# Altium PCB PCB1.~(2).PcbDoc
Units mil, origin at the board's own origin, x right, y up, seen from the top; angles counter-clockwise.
Board outline 1968 x 1968 mil, 4 copper layers (Top Layer, Internal Plane 1, Internal Plane 2, Bottom Layer), stack 18.2 mil thick; 12 components, 11 nets, 37 pads, 0 vias.
Unrouted connection lines stored in the file: 6.
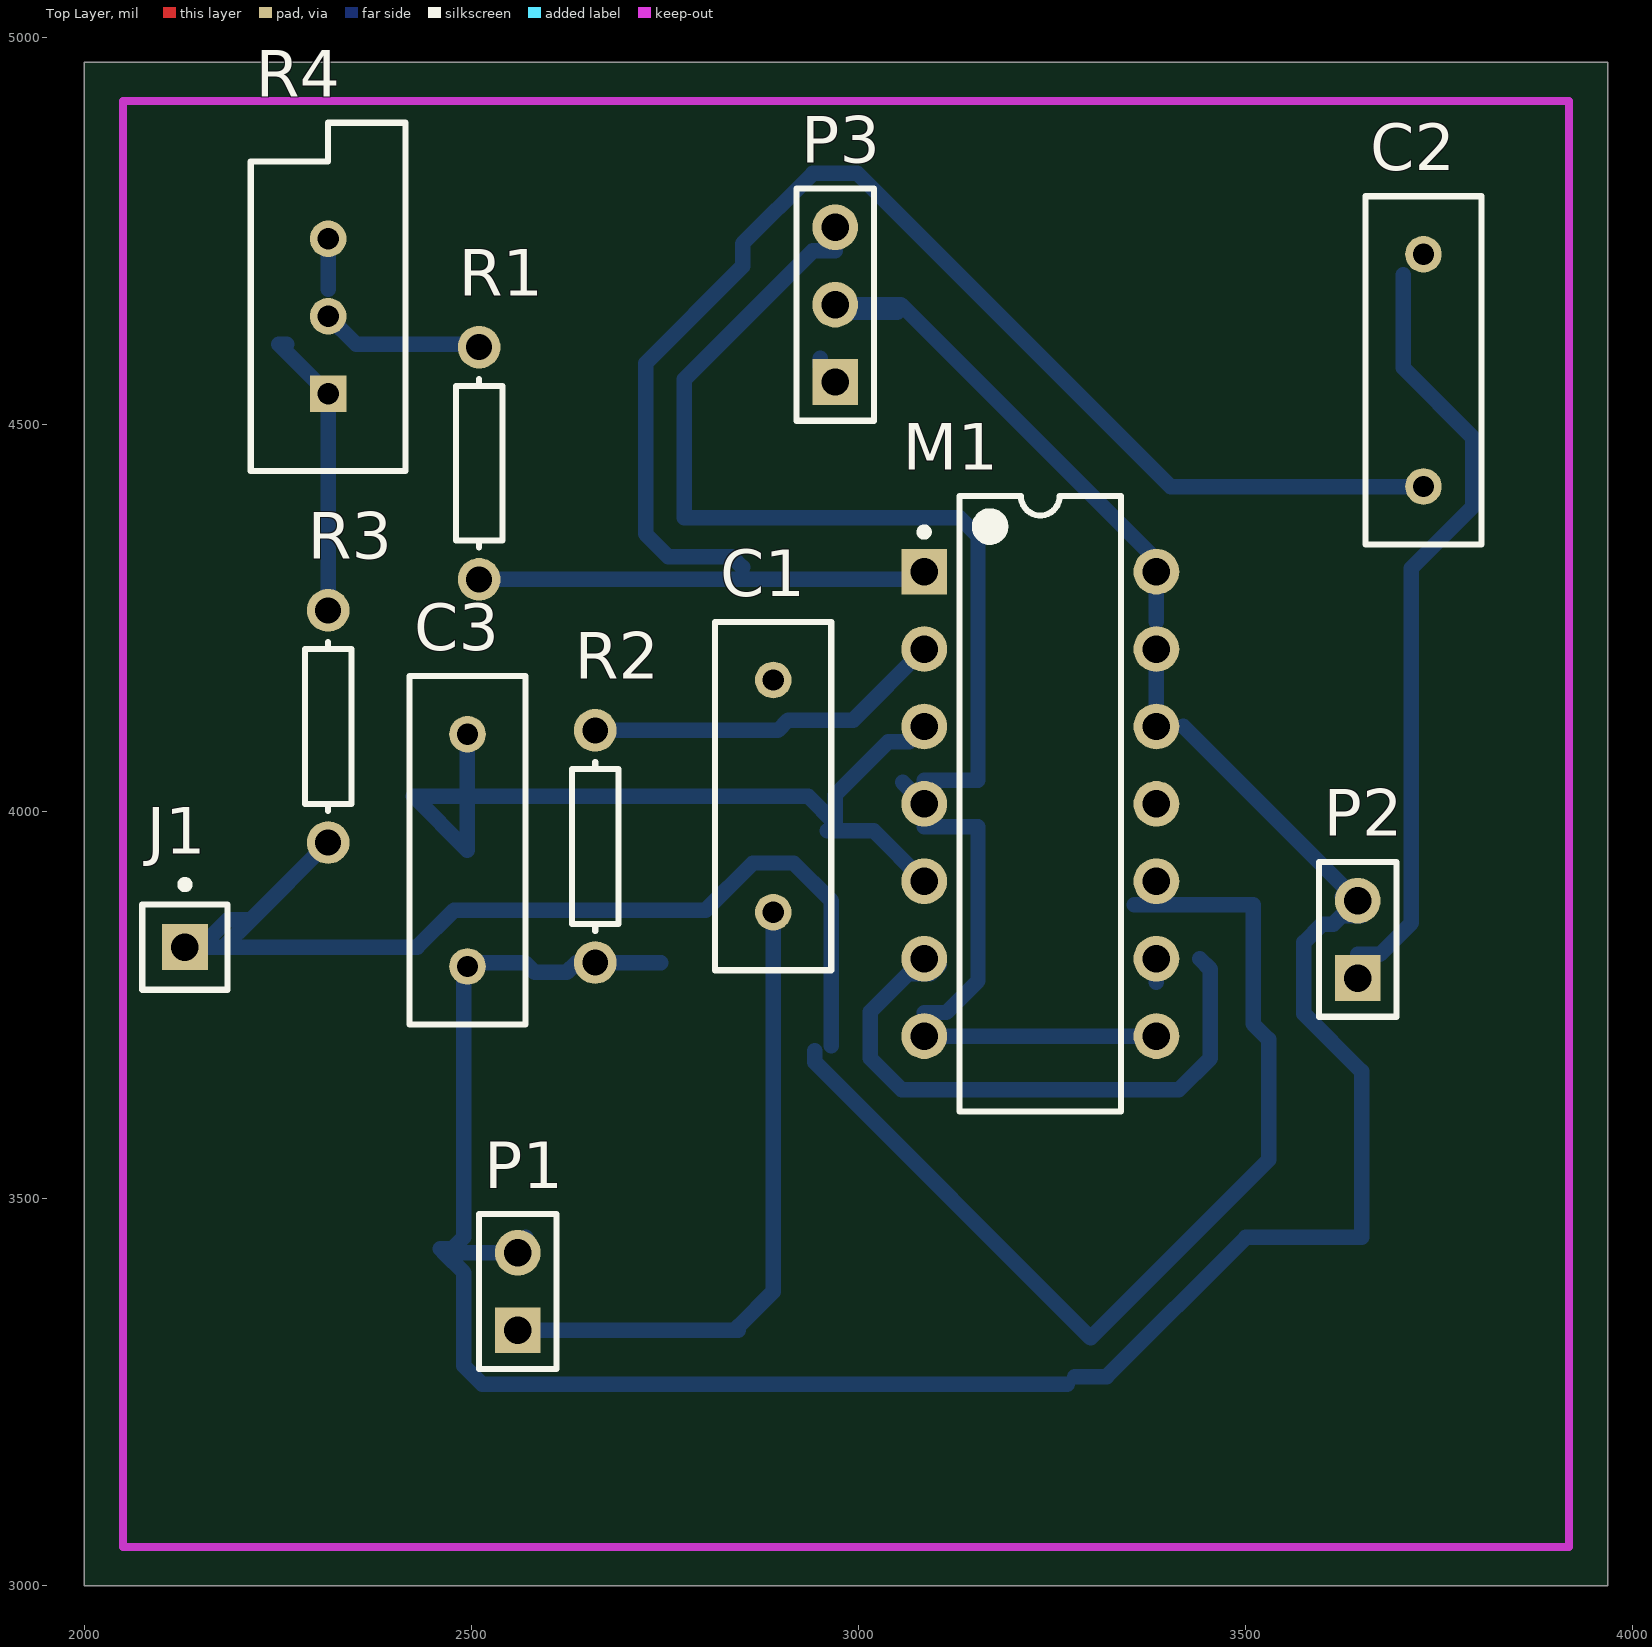
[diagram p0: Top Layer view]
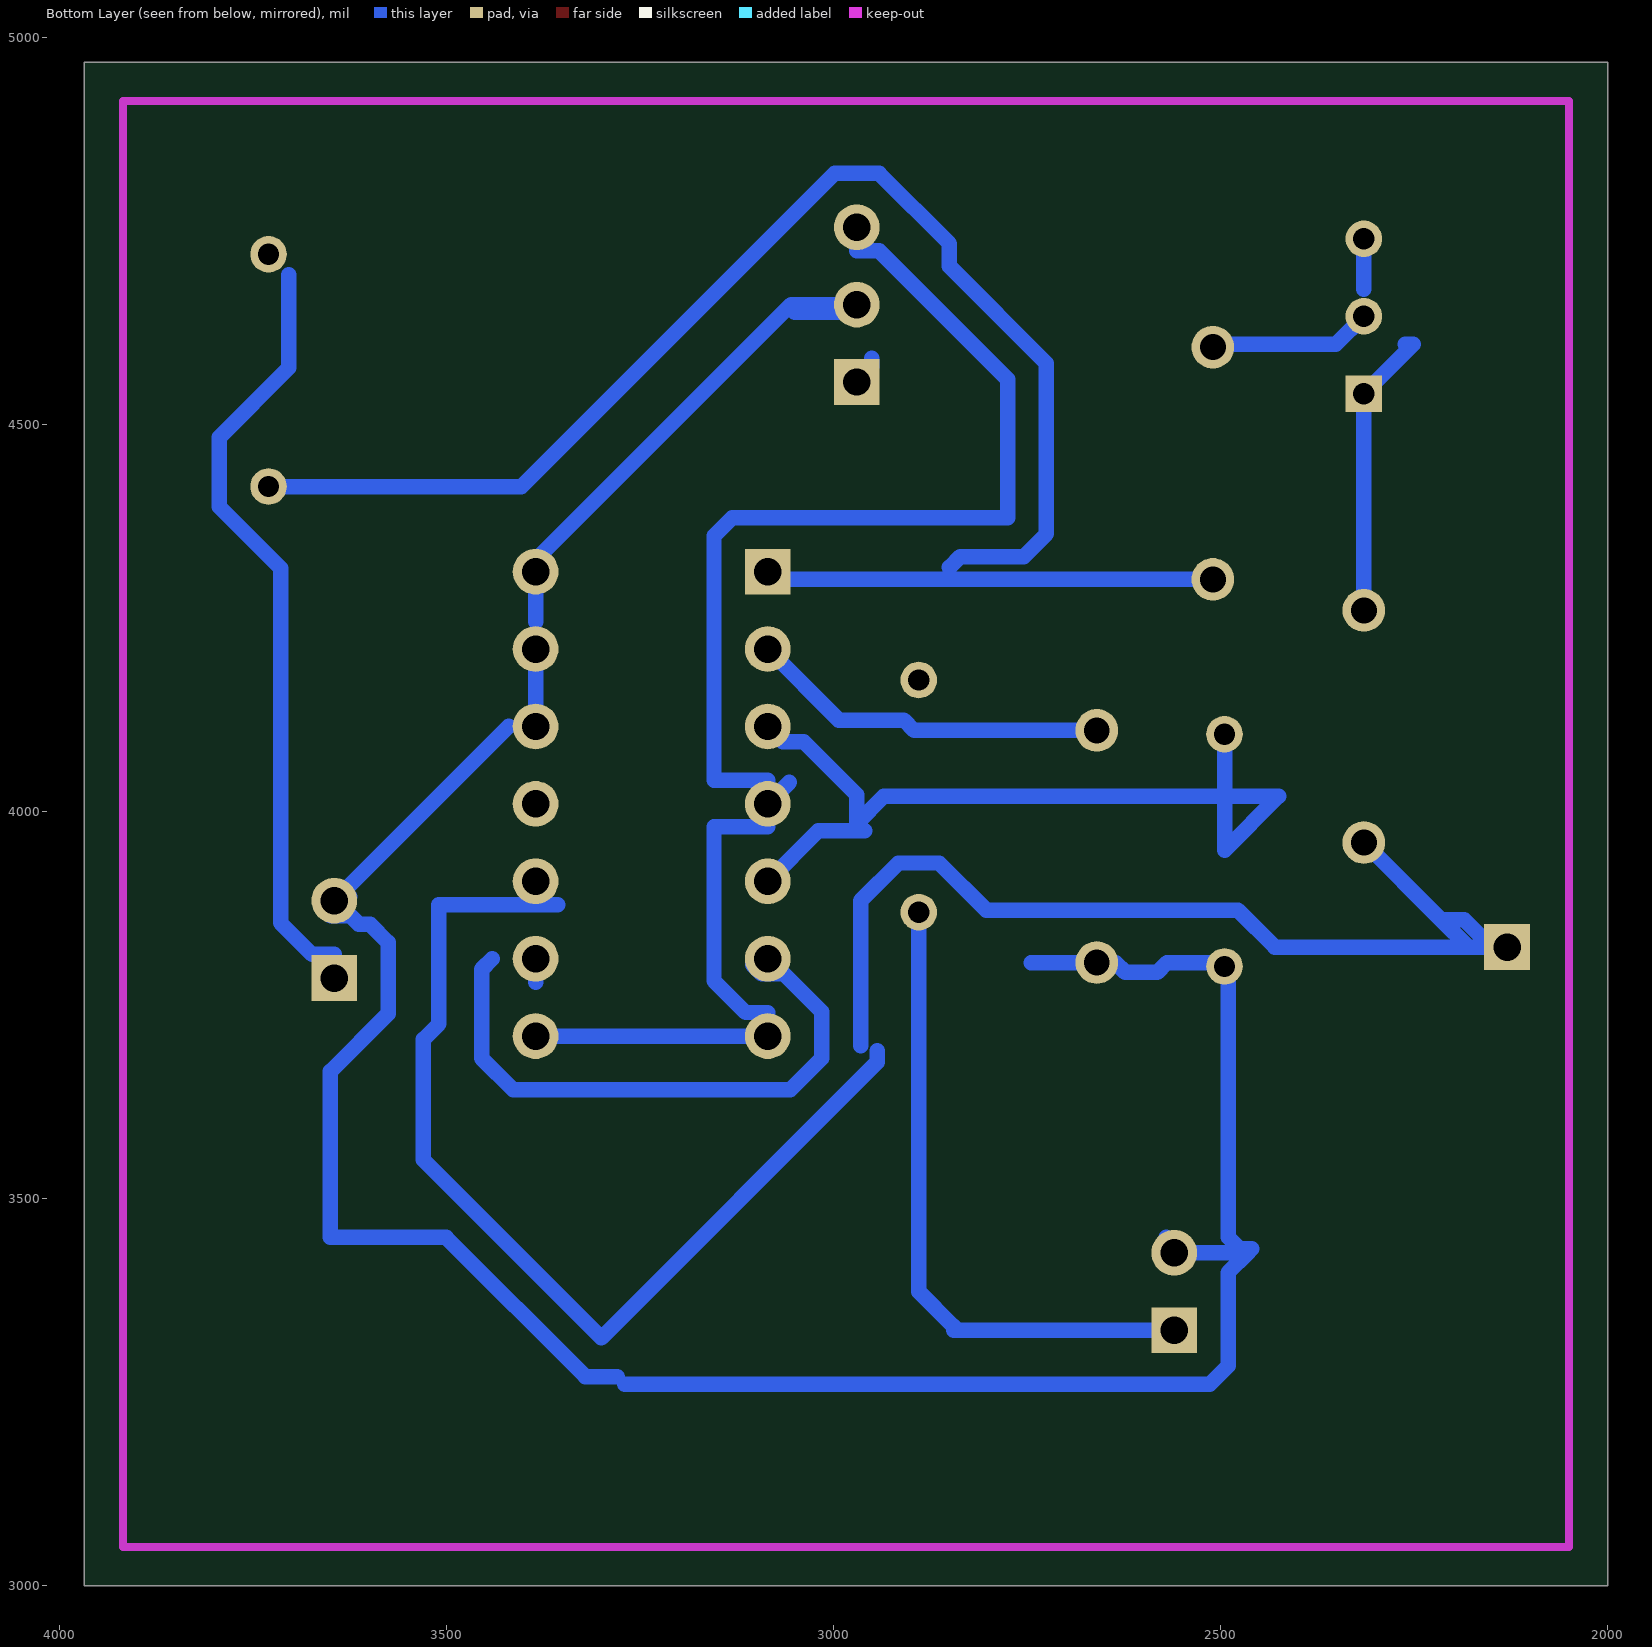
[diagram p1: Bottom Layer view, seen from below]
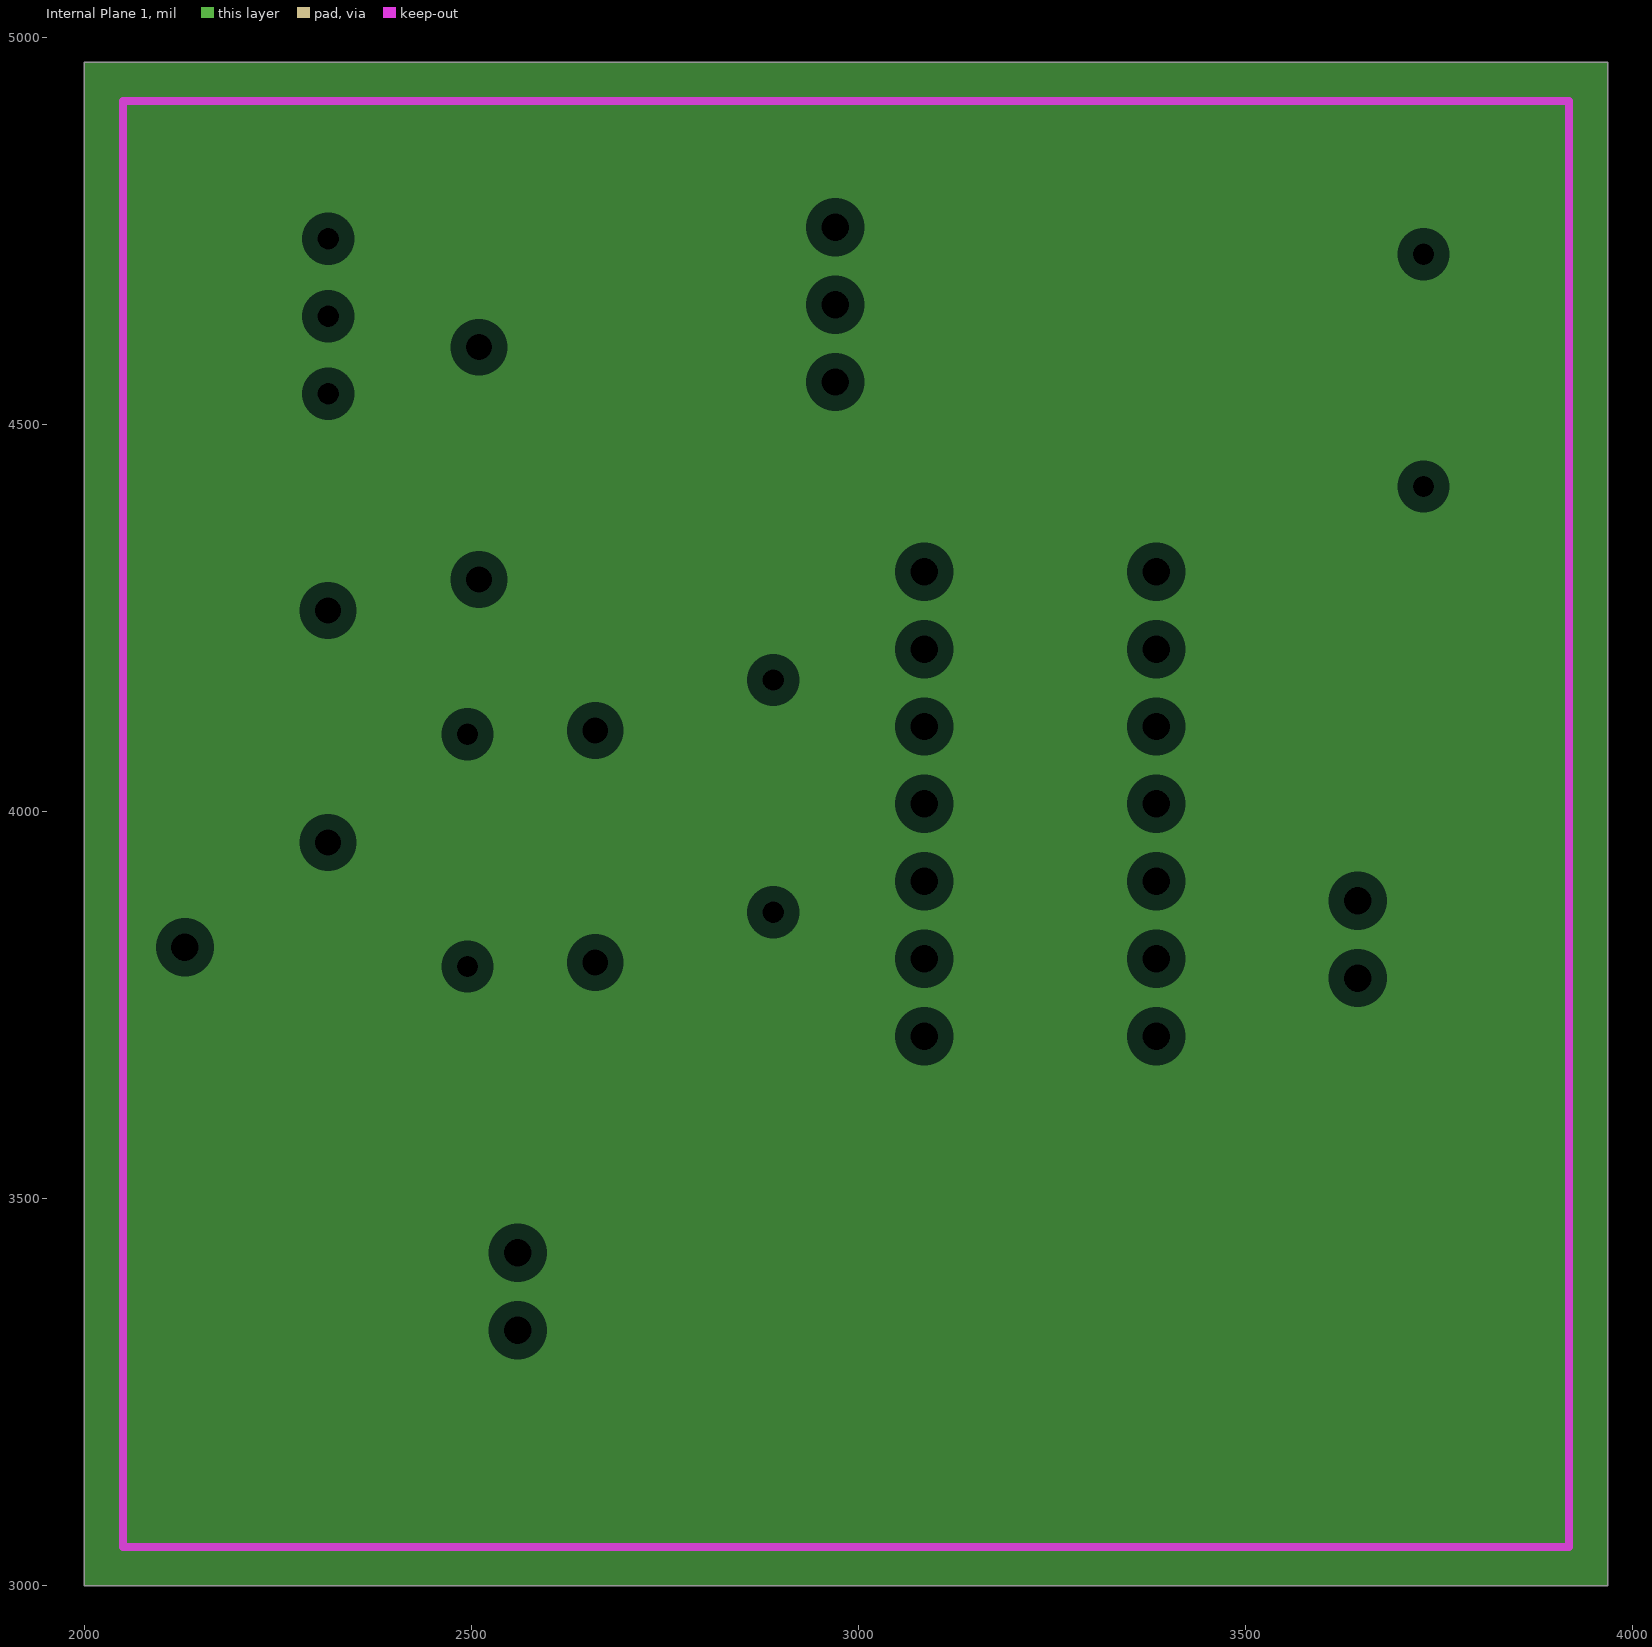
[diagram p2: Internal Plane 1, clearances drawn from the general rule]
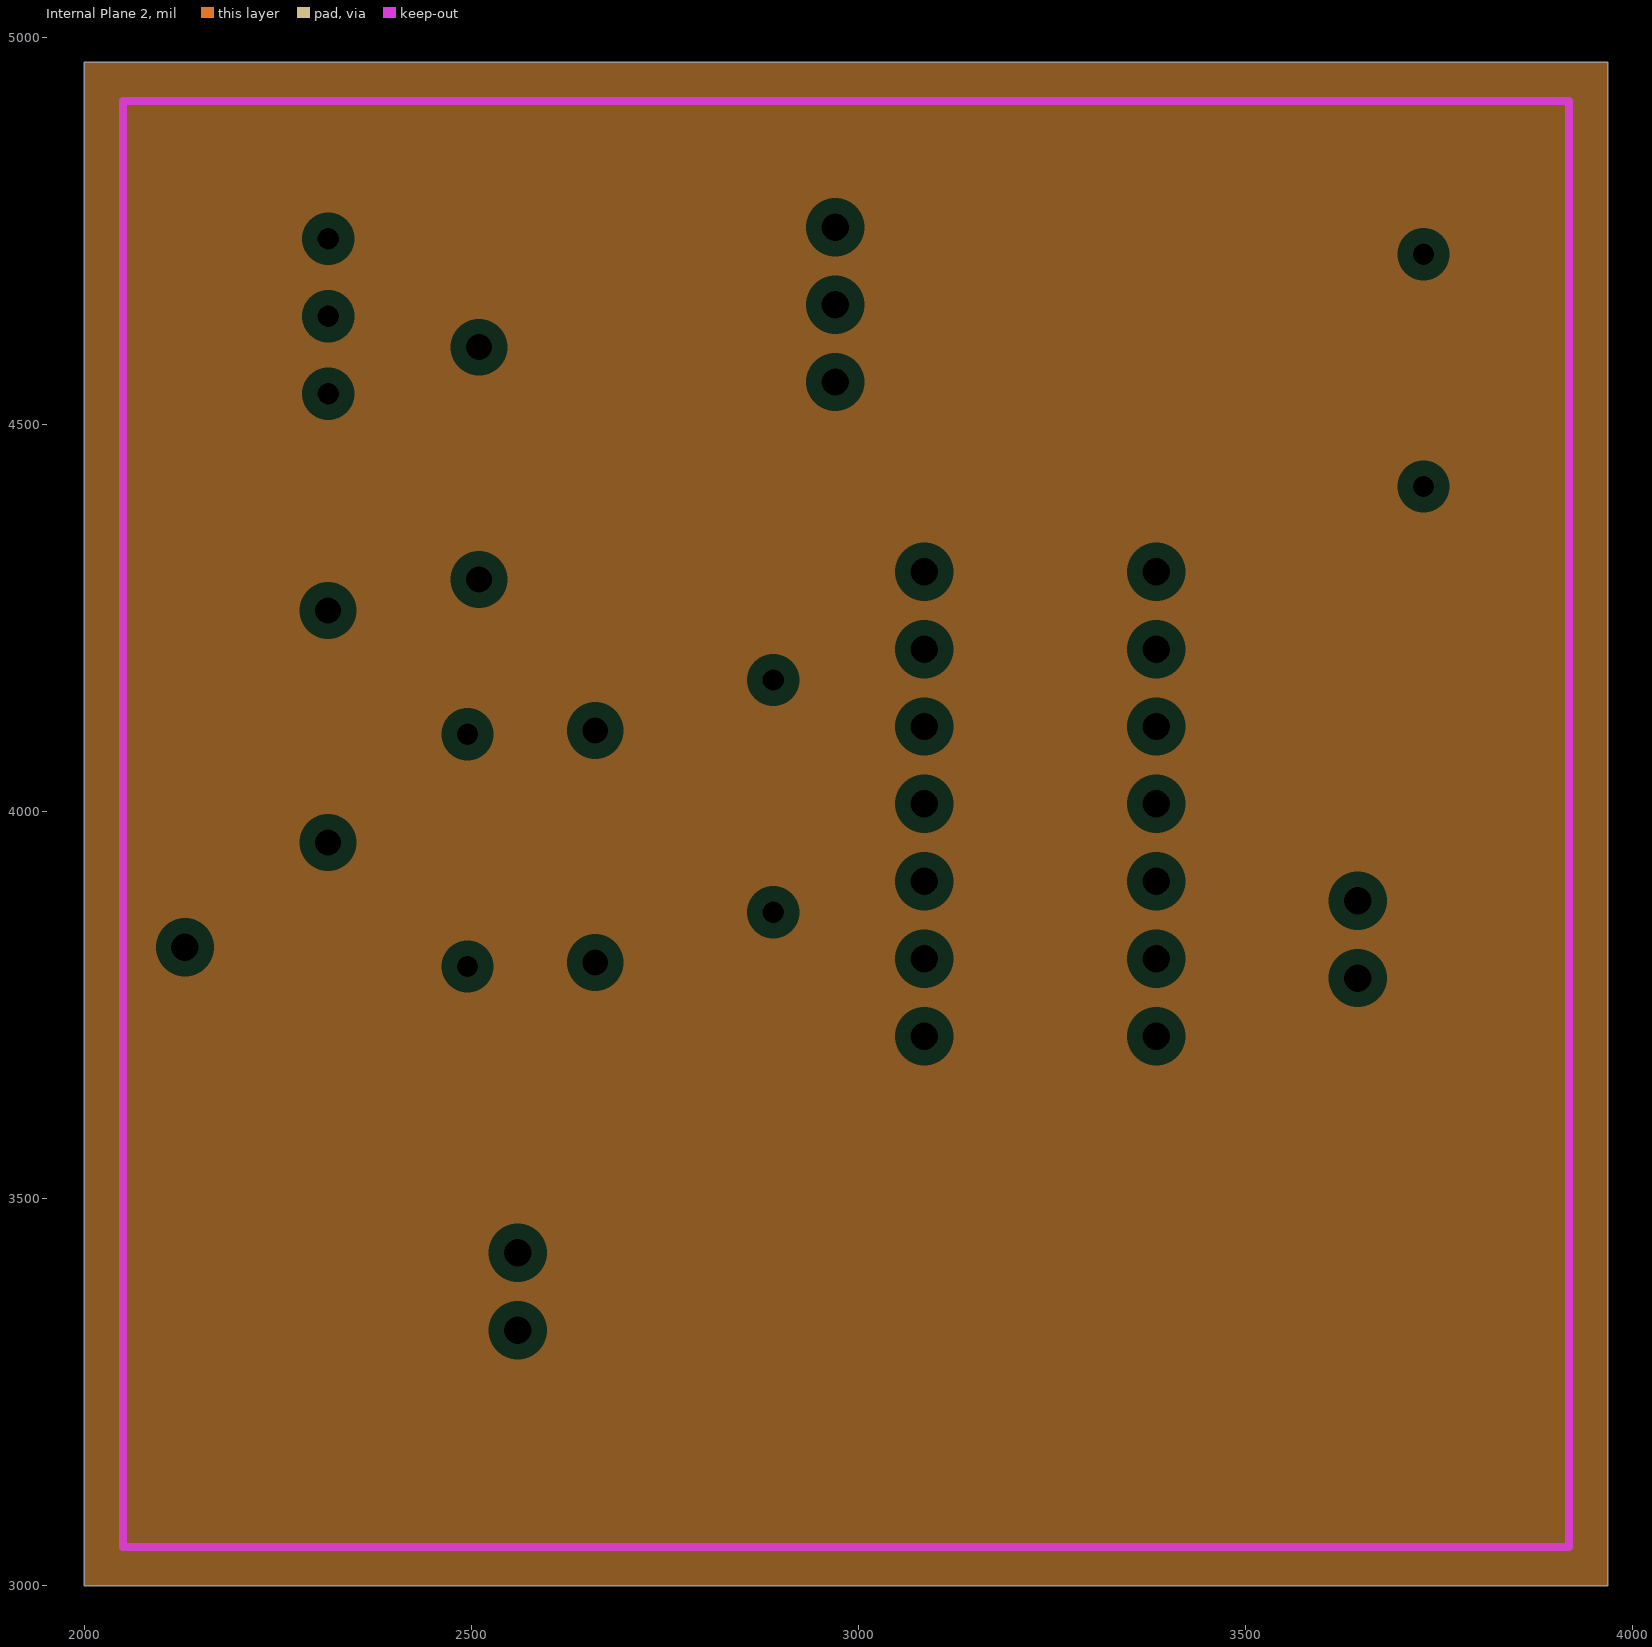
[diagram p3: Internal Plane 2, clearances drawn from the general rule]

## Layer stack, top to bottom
Top Solder: solder mask 0.4, Solder Resist, Dk 3.5
Top Layer: signal copper 1.4
Internal Plane 1: plane copper 1.4
Internal Plane 2: plane copper 1.4
Dielectric 1: dielectric 12.6, FR-4, Dk 4.8
Bottom Layer: signal copper 1.4
Bottom Solder: solder mask 0.4, Solder Resist, Dk 3.5

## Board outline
2000,3000 3968,3000 3968,4968 2000,4968

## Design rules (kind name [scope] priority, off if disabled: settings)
Clearance [All] p1: gap=30
PlaneClearance [All] p1: clearance=20
PlaneConnect [All] p1: planeconnectstyle=Relief reliefexpansion=20 reliefentries=4 reliefconductorwidth=10 reliefairgap=10
PolygonConnect [All] p1: connectstyle=Relief reliefconductorwidth=10 reliefentries=4 polygonreliefangle="90 Angle" airgapwidth=10
RoutingVias [All] p1: holewidth=32 width=62 viastyle="Through Hole" minholewidth=28 minwidth=50 maxholewidth=28 maxwidth=50
SolderMaskExpansion [All] p1: expansion=4
Width [All] p1: maxlimit=20 minlimit=20 preferedwidth=20
28 further rules are at their usual default settings.

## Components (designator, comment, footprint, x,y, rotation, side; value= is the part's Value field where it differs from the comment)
C1 "Cap" RAD-0.3 2890,4020 r90 top
C2 "Cap" RAD-0.3 3730,4570 r90 top
C3 "Cap" RAD-0.3 2495,3950 r90 top
J1 "Socket" PIN1 2130,3825 r0 top
M1 "ALD1106" DIP-14 3235,4010 r0 top
P1 "Header 2" HDR1X2 2560,3330 r90 top
P2 "Header 2" HDR1X2 3645,3785 r90 top
P3 "Header 3" HDR1X3 2970,4555 r90 top
R1 "Res1" AXIAL-0.3 2510,4450 r90 top
R2 "Res1" AXIAL-0.3 2660,3955 r90 top
R3 "Res1" AXIAL-0.3 2315,4110 r90 top
R4 "RPot" VR5 2315,4640 r90 top

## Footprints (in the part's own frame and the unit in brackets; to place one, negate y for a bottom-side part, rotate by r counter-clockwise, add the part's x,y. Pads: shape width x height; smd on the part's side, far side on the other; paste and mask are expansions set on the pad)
AXIAL-0.3 [mm] "Axial Device, Thru-Hole; 2 Leads; 0.3 in Pin Spacing"
  round 1.4 hole 0.85: 1(-3.81,0) 2(3.81,0)
  silkscreen extent -2.77,-0.76 2.77,0.76
DIP-14 [mm] "DIP, 14-Pin, Row Spacing 7.62 mm, Pitch 2.54 mm"
  rect 1.5x1.5 hole 0.9: 1(-3.81,7.62)
  round 1.5 hole 0.9: 2(-3.81,5.08) 3(-3.81,2.54) 4(-3.81,0) 5(-3.81,-2.54) 6(-3.81,-5.08) 7(-3.81,-7.62) 8(3.81,-7.62) 9(3.81,-5.08) 10(3.81,-2.54) 11(3.81,0) 12(3.81,2.54) 13(3.81,5.08) 14(3.81,7.62)
  silkscreen extent -3.93,-10.1 2.65,10.1, body extent -3.6,-10.1 3.6,10.1, height 5.08
HDR1X2 [mm] "Connector; Header; 2 Position"
  rect 1.5x1.5 hole 0.9: 1(0,0)
  round 1.5 hole 0.9: 2(2.54,0)
  silkscreen extent -1.27,-1.27 3.81,1.27
HDR1X3 [mm] "Connector; Header; 3 Position"
  rect 1.5x1.5 hole 0.9: 1(0,0)
  round 1.5 hole 0.9: 2(2.54,0) 3(5.08,0)
  silkscreen extent -1.27,-1.27 6.35,1.27
PIN1 [mm] "Connector; Plug"
  rect 1.5x1.5 hole 0.9: 1(0,0)
  silkscreen extent -1.4,-1.4 1.4,2.17
RAD-0.3 [mm] "Radial Cap, Thru-Hole; 2 Leads; 0.3 in Pin Spacing"
  round 1.2 hole 0.7: 1(-3.81,0) 2(3.81,0)
  silkscreen extent -5.71,-1.91 5.71,1.91
VR5 [mm] "Thru-Hole; 3 Leads"
  rect 1.2x1.2 hole 0.7: 1(-2.54,0)
  round 1.2 hole 0.7: 2(0,0) 3(2.54,0)
  silkscreen extent -5.08,-2.54 6.35,2.54

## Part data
C1 C2 C3: "Capacitor"
M1: "Quad N-channel matched MOSFET array"
P1 P2: "Header, 2-Pin"
P3: "Header, 3-Pin"
R1 R2 R3: "Resistor"
R4: "Potentiometer"

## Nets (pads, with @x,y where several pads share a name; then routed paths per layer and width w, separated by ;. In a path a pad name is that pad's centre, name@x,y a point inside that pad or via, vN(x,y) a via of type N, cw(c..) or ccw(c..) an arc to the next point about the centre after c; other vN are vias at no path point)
GND: C3.1 M1.12 M1.13 M1.14 P1.2 P2.2 P3.2 R2.1 | length 3856.8
  Bottom Layer w20: C3.1 2490,3800 2490,3450 2475,3435 2460,3435 2465,3430 ; C3.1@2500,3805 2569.29,3805 2581.79,3792.5 2623.21,3792.5 2635.71,3805 2745,3805 ; P1.2@2555,3435 P1.2@2570,3450 ; P1.2 2465,3430 ; 3050,4645 2960,4645 P3.2 3055,4655 M1.14@3385,4325 ; 3269.76,3260.47 2513.9,3260.47 2490.47,3283.9 2490.47,3404.53 2465,3430 ; 3279.29,3270 3320.71,3270 3500.71,3450 3650,3450 3650,3664.38 3575.47,3738.9 3575.47,3831.1 3598.9,3854.53 3613.34,3854.53 3624.29,3865.47 3649.53,3865.47 P2.2@3625,3890 ; M1.12 M1.13 ; 3385,4245 3385,4305 3390,4305 M1.14 ; 3420,4110 P2.2 P2.2@3630,3885
NetC1_1: C1.1 P1.1 | length 838.6
  Bottom Layer w20: P1.1 2845,3330 ; 2845,3335 2890,3380 C1.1
NetC1_2: C1.2 M1.2 R2.2 | length 463.5
  Bottom Layer w20: R2.2 2740,4105 ; 2745,4105 2895.96,4105 2909.29,4118.33 2993.33,4118.33 M1.2
NetC2_1: C2.1 M1.1 R1.1 | length 2234.2
  Bottom Layer w20: R1.1 3075,4300 M1.1 ; 2850.47,4315.47 2836.42,4329.53 2754.29,4329.53 2725,4358.82 2725,4579.04 2850.47,4704.51 2850.47,4733.8 2941.2,4824.53 2998.8,4824.53 3403.33,4420 C2.1
NetC2_2: C2.2 P2.1 | length 1024.3
  Bottom Layer w20: P2.1 3645,3815.47 3673.8,3815.47 3714.53,3856.2 3714.53,4314.55 3793.62,4393.65 3793.62,4483.62 3703.65,4573.6 3703.65,4693.65
NetC3_2: C3.2 M1.3 M1.5 | length 1148.6
  Bottom Layer w20: C3.2 2495,3950 2425,4020 2935,4020 2970,3985 2970,4021.61 3038.86,4090.47 3065.47,4090.47 M1.3 ; 2960,3975 3020,3975 M1.5
NetJ1_1: J1.1 M1.10 R3.1 | length 2724.1
  Bottom Layer w20: J1.1 J1.1@2150,3825 ; R3.1 2215,3860 ; 2943.62,3691.35 2943.62,3676.38 3300,3320 3530,3550 3530,3705.73 3510,3725.73 3510,3879.53 3356.2,3879.53 ; 2964.98,3697.73 2964.98,3885 2916.35,3933.62 2863.65,3933.62 2802.58,3872.56 2477.58,3872.56 2430.02,3825 2180,3825 ; 3385,3879.53 M1.10 ; J1.1@2150,3825 2180,3825 ; J1.1@2150,3825 2185,3860 2215,3860 ; 2180,3825 2215,3860
NetM1_4: M1.4 M1.7 M1.8 P3.3 | length 1998.4
  Bottom Layer w20: P3.3 2970,4724.53 2941.2,4724.53 2775,4558.33 2775,4379.53 3131.1,4379.53 3154.53,4356.1 3154.53,4040.47 3085,4040.47 ; 3057.05,4037.95 M1.4 M1.4@3085,4035.47 ; M1.4@3085,3980.71 3154.53,3980.71 3154.53,3781.2 3113.8,3740.47 3085,3740.47 M1.7 M1.8
NetM1_6: M1.6 M1.9 | length 839.8
  Bottom Layer w20: M1.6 3104.53,3810 3104.53,3801.91 3093.09,3790.47 3064.29,3790.47 3015.47,3741.66 3015.47,3681.2 3056.2,3640.47 3413.8,3640.47 3454.53,3681.2 3454.53,3796.37 3440.9,3810 ; 3385,3779.53 M1.9
NetP3_1: P3.1 R1.2 R4.2 R4.3 | length 315.1
  Bottom Layer w20: R4.2 2351.38,4603.62 2506.38,4603.62 R1.2 ; 2315,4675 R4.3 ; 2950.47,4585.47 2950.47,4574.53 P3.1
NetR3_2: R3.2 R4.1 | length 370
  Bottom Layer w20: 2261.4,4603.62 2251.38,4603.62 R4.1 R3.2@2315,4270
pads on no net: M1.11

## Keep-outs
Keep-Out Layer:
  lines w10: 2050,3050 2050,4918 3918,4918 3918,3050 2050,3050

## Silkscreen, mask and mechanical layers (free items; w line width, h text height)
Drill Drawing:
  text ".LEGEND" at 1863,3640 h60
  text "Drill Drawing." at 1863,3540 h60

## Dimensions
2050,3050 to 2050,4918 on Mechanical 1
2050,3050 to 3918,3050 on Mechanical 1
